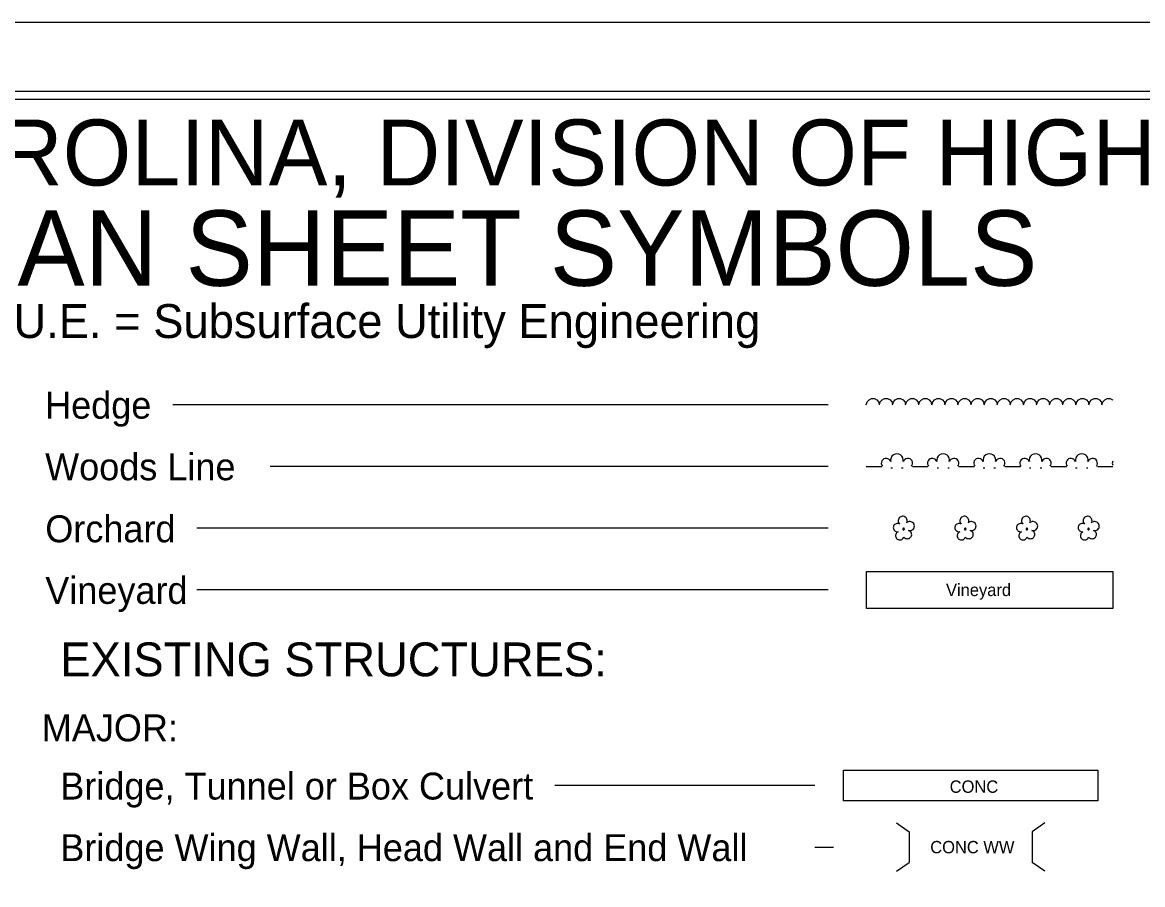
# Model space of a CAD drawing. Extents: x 1729964 to 1731648, y 539487 to 540587.
# Drawn here: x 1730887.2 to 1731250.8, y 540307.4 to 540587.4 of the extents above; entities that cross this region are included whole.
import ezdxf

# ---------------------------------------------------------------- set-up
doc = ezdxf.new("R2010")
doc.units = 0
for name, color, linetype in [('Sheet Cutting Line CELL', 7, 'Continuous'), ('Sheet Plot Border Inside CELL', 7, 'Continuous'), ('Sheet Plot Border Outside CELL', 7, 'Continuous'), ('Sheet Symbology CELL', 7, 'Continuous')]:
    doc.layers.add(name, color=color, linetype=linetype)

msp = doc.modelspace()

# ---------------------------------------------------------------- linework, layer by layer
at = {"layer": 'Sheet Cutting Line CELL'}
msp.add_line((1731648.46, 540587.38), (1729964.46, 540587.38), dxfattribs=at)
at = {"layer": 'Sheet Plot Border Inside CELL'}
msp.add_lwpolyline([(1729977.46, 539509.83), (1731643.96, 539509.83), (1731643.96, 540564.93), (1729977.46, 540564.93)], close=True, dxfattribs=at)
at = {"layer": 'Sheet Plot Border Outside CELL'}
msp.add_lwpolyline([(1729964.46, 539487.38), (1731648.46, 539487.38), (1731648.46, 540587.38), (1729964.46, 540587.38)], close=True, dxfattribs=at)
at = {"layer": 'Sheet Symbology CELL'}
for p, q in [((1731148.74, 540463.23), (1730936.06, 540463.23)), ((1731161.14, 540463.23), (1731161.44, 540464.18)), ((1731161.44, 540464.18), (1731162.04, 540464.83)), ((1731162.04, 540464.83), (1731162.84, 540465.28)), ((1731162.84, 540465.28), (1731163.79, 540465.28)), ((1731163.79, 540465.28), (1731164.59, 540464.78)), ((1731164.59, 540464.78), (1731165.14, 540464.13)), ((1731165.14, 540464.13), (1731165.34, 540463.28)), ((1731165.39, 540463.23), (1731165.69, 540464.18)), ((1731165.69, 540464.18), (1731166.29, 540464.83)), ((1731166.29, 540464.83), (1731167.09, 540465.28)), ((1731167.09, 540465.28), (1731168.04, 540465.28)), ((1731168.04, 540465.28), (1731168.84, 540464.78)), ((1731168.84, 540464.78), (1731169.39, 540464.13)), ((1731169.39, 540464.13), (1731169.59, 540463.28)), ((1731169.64, 540463.23), (1731169.94, 540464.18)), ((1731169.94, 540464.18), (1731170.54, 540464.83)), ((1731170.54, 540464.83), (1731171.34, 540465.28)), ((1731171.34, 540465.28), (1731172.29, 540465.28)), ((1731172.29, 540465.28), (1731173.09, 540464.78)), ((1731173.09, 540464.78), (1731173.64, 540464.13)), ((1731173.64, 540464.13), (1731173.84, 540463.28)), ((1731173.89, 540463.23), (1731174.19, 540464.18)), ((1731174.19, 540464.18), (1731174.79, 540464.83)), ((1731174.79, 540464.83), (1731175.59, 540465.28)), ((1731175.59, 540465.28), (1731176.54, 540465.28)), ((1731176.54, 540465.28), (1731177.34, 540464.78)), ((1731177.34, 540464.78), (1731177.89, 540464.13)), ((1731177.89, 540464.13), (1731178.09, 540463.28)), ((1731178.14, 540463.23), (1731178.44, 540464.18)), ((1731178.44, 540464.18), (1731179.04, 540464.83)), ((1731179.04, 540464.83), (1731179.84, 540465.28)), ((1731179.84, 540465.28), (1731180.79, 540465.28)), ((1731180.79, 540465.28), (1731181.59, 540464.78)), ((1731181.59, 540464.78), (1731182.14, 540464.13)), ((1731182.14, 540464.13), (1731182.34, 540463.28)), ((1731182.39, 540463.23), (1731182.69, 540464.18)), ((1731182.69, 540464.18), (1731183.29, 540464.83)), ((1731183.29, 540464.83), (1731184.09, 540465.28)), ((1731184.09, 540465.28), (1731185.04, 540465.28)), ((1731185.04, 540465.28), (1731185.84, 540464.78)), ((1731185.84, 540464.78), (1731186.39, 540464.13)), ((1731186.39, 540464.13), (1731186.59, 540463.28)), ((1731186.64, 540463.23), (1731186.94, 540464.18)), ((1731186.94, 540464.18), (1731187.54, 540464.83)), ((1731187.54, 540464.83), (1731188.34, 540465.28)), ((1731188.34, 540465.28), (1731189.29, 540465.28)), ((1731189.29, 540465.28), (1731190.09, 540464.78)), ((1731190.09, 540464.78), (1731190.64, 540464.13)), ((1731190.64, 540464.13), (1731190.84, 540463.28)), ((1731190.89, 540463.23), (1731191.19, 540464.18)), ((1731191.19, 540464.18), (1731191.79, 540464.83)), ((1731191.79, 540464.83), (1731192.59, 540465.28)), ((1731192.59, 540465.28), (1731193.54, 540465.28)), ((1731193.54, 540465.28), (1731194.34, 540464.78)), ((1731194.34, 540464.78), (1731194.89, 540464.13)), ((1731194.89, 540464.13), (1731195.09, 540463.28)), ((1731195.14, 540463.23), (1731195.44, 540464.18)), ((1731195.44, 540464.18), (1731196.04, 540464.83)), ((1731196.04, 540464.83), (1731196.84, 540465.28)), ((1731196.84, 540465.28), (1731197.79, 540465.28)), ((1731197.79, 540465.28), (1731198.59, 540464.78)), ((1731198.59, 540464.78), (1731199.14, 540464.13)), ((1731199.14, 540464.13), (1731199.34, 540463.28)), ((1731199.39, 540463.23), (1731199.69, 540464.18)), ((1731199.69, 540464.18), (1731200.29, 540464.83)), ((1731200.29, 540464.83), (1731201.09, 540465.28)), ((1731201.09, 540465.28), (1731202.04, 540465.28)), ((1731202.04, 540465.28), (1731202.84, 540464.78)), ((1731202.84, 540464.78), (1731203.39, 540464.13)), ((1731203.39, 540464.13), (1731203.59, 540463.28)), ((1731203.64, 540463.23), (1731203.94, 540464.18)), ((1731203.94, 540464.18), (1731204.54, 540464.83)), ((1731204.54, 540464.83), (1731205.34, 540465.28)), ((1731205.34, 540465.28), (1731206.29, 540465.28)), ((1731206.29, 540465.28), (1731207.09, 540464.78)), ((1731207.09, 540464.78), (1731207.64, 540464.13)), ((1731207.64, 540464.13), (1731207.84, 540463.28)), ((1731207.89, 540463.23), (1731208.19, 540464.18)), ((1731208.19, 540464.18), (1731208.79, 540464.83)), ((1731208.79, 540464.83), (1731209.59, 540465.28)), ((1731209.59, 540465.28), (1731210.54, 540465.28)), ((1731210.54, 540465.28), (1731211.34, 540464.78)), ((1731211.34, 540464.78), (1731211.89, 540464.13)), ((1731211.89, 540464.13), (1731212.09, 540463.28)), ((1731212.14, 540463.23), (1731212.44, 540464.18)), ((1731212.44, 540464.18), (1731213.04, 540464.83)), ((1731213.04, 540464.83), (1731213.84, 540465.28)), ((1731213.84, 540465.28), (1731214.79, 540465.28)), ((1731214.79, 540465.28), (1731215.59, 540464.78)), ((1731215.59, 540464.78), (1731216.14, 540464.13)), ((1731216.14, 540464.13), (1731216.34, 540463.28)), ((1731216.39, 540463.23), (1731216.69, 540464.18)), ((1731216.69, 540464.18), (1731217.29, 540464.83)), ((1731217.29, 540464.83), (1731218.09, 540465.28)), ((1731218.09, 540465.28), (1731219.04, 540465.28)), ((1731219.04, 540465.28), (1731219.84, 540464.78)), ((1731219.84, 540464.78), (1731220.39, 540464.13)), ((1731220.39, 540464.13), (1731220.59, 540463.28)), ((1731220.64, 540463.23), (1731220.94, 540464.18)), ((1731220.94, 540464.18), (1731221.54, 540464.83)), ((1731221.54, 540464.83), (1731222.34, 540465.28)), ((1731222.34, 540465.28), (1731223.29, 540465.28)), ((1731223.29, 540465.28), (1731224.09, 540464.78)), ((1731224.09, 540464.78), (1731224.64, 540464.13)), ((1731224.64, 540464.13), (1731224.84, 540463.28)), ((1731224.89, 540463.23), (1731225.19, 540464.18)), ((1731225.19, 540464.18), (1731225.79, 540464.83)), ((1731225.79, 540464.83), (1731226.59, 540465.28)), ((1731226.59, 540465.28), (1731227.54, 540465.28)), ((1731227.54, 540465.28), (1731228.34, 540464.78)), ((1731228.34, 540464.78), (1731228.89, 540464.13)), ((1731228.89, 540464.13), (1731229.09, 540463.28)), ((1731229.14, 540463.23), (1731229.44, 540464.18)), ((1731229.44, 540464.18), (1731230.04, 540464.83)), ((1731230.04, 540464.83), (1731230.84, 540465.28)), ((1731230.84, 540465.28), (1731231.79, 540465.28)), ((1731231.79, 540465.28), (1731232.59, 540464.78)), ((1731232.59, 540464.78), (1731233.14, 540464.13)), ((1731233.14, 540464.13), (1731233.34, 540463.28)), ((1731233.39, 540463.23), (1731233.69, 540464.18)), ((1731233.69, 540464.18), (1731234.29, 540464.83)), ((1731234.29, 540464.83), (1731235.09, 540465.28)), ((1731235.09, 540465.28), (1731236.04, 540465.28)), ((1731236.04, 540465.28), (1731236.84, 540464.78)), ((1731236.84, 540464.78), (1731237.39, 540464.13)), ((1731237.39, 540464.13), (1731237.59, 540463.28)), ((1731237.64, 540463.23), (1731237.94, 540464.18)), ((1731237.94, 540464.18), (1731238.54, 540464.83)), ((1731238.54, 540464.83), (1731239.34, 540465.28)), ((1731239.34, 540465.28), (1731240.29, 540465.28)), ((1731240.29, 540465.28), (1731241.09, 540464.78)), ((1731241.09, 540464.78), (1731241.14, 540464.73)), ((1731148.74, 540443.23), (1730967.62, 540443.23)), ((1731161.14, 540443.23), (1731166.14, 540443.23)), ((1731169.09, 540442.73), (1731169.59, 540442.73)), ((1731172.59, 540442.73), (1731173.09, 540442.73)), ((1731176.14, 540443.23), (1731181.14, 540443.23)), ((1731184.09, 540442.73), (1731184.59, 540442.73)), ((1731187.59, 540442.73), (1731188.09, 540442.73)), ((1731191.14, 540443.23), (1731196.14, 540443.23)), ((1731199.09, 540442.73), (1731199.59, 540442.73)), ((1731202.59, 540442.73), (1731203.09, 540442.73)), ((1731206.14, 540443.23), (1731211.14, 540443.23)), ((1731214.09, 540442.73), (1731214.59, 540442.73)), ((1731217.59, 540442.73), (1731218.09, 540442.73)), ((1731221.14, 540443.23), (1731226.14, 540443.23)), ((1731229.09, 540442.73), (1731229.59, 540442.73)), ((1731232.59, 540442.73), (1731233.09, 540442.73)), ((1731236.14, 540443.23), (1731241.14, 540443.23)), ((1731148.79, 540423.1), (1730943.85, 540423.1)), ((1731148.79, 540403.1), (1730943.85, 540403.1)), ((1731144.48, 540339.59), (1731060.05, 540339.59)), ((1731170.93, 540327.45), (1731175.03, 540324.59)), ((1731219.13, 540327.45), (1731215.03, 540324.59)), ((1731175.03, 540324.59), (1731175.03, 540314.59)), ((1731215.03, 540324.59), (1731215.03, 540314.59)), ((1731144.48, 540319.59), (1731150.46, 540319.59)), ((1731170.93, 540311.73), (1731175.03, 540314.59)), ((1731219.13, 540311.73), (1731215.03, 540314.59))]:
    msp.add_line(p, q, dxfattribs=at)
msp.add_lwpolyline([(1731631.46, 540562.38), (1730131.46, 540562.38), (1730131.46, 539513.4), (1731631.46, 539513.4)], close=True, dxfattribs=at)
for points in [[(1731174.23, 540424.85), (1731174.38, 540425.15), (1731174.43, 540425.45), (1731174.38, 540425.75), (1731174.33, 540426.05), (1731174.18, 540426.3), (1731174.03, 540426.55), (1731173.78, 540426.75), (1731173.53, 540426.9), (1731173.18, 540427), (1731172.93, 540427), (1731172.63, 540426.95), (1731172.33, 540426.85), (1731172.08, 540426.7), (1731171.83, 540426.5), (1731171.68, 540426.2), (1731171.58, 540425.95), (1731171.53, 540425.65), (1731171.53, 540425.35), (1731171.58, 540425.05), (1731171.73, 540424.8), (1731171.93, 540424.5), (1731171.68, 540424.65), (1731171.38, 540424.7), (1731171.08, 540424.7), (1731170.83, 540424.6), (1731170.58, 540424.5), (1731170.33, 540424.3), (1731170.13, 540424.1), (1731169.98, 540423.85), (1731169.93, 540423.6), (1731169.88, 540423.25), (1731169.93, 540423), (1731170.03, 540422.75), (1731170.23, 540422.5), (1731170.38, 540422.3), (1731170.63, 540422.15), (1731170.93, 540422), (1731171.18, 540421.95), (1731171.48, 540421.95), (1731171.23, 540421.85), (1731170.98, 540421.65), (1731170.83, 540421.45), (1731170.73, 540421.15), (1731170.63, 540420.85), (1731170.63, 540420.6), (1731170.68, 540420.3), (1731170.83, 540420.05), (1731170.98, 540419.8), (1731171.18, 540419.6), (1731171.43, 540419.45), (1731171.68, 540419.35), (1731171.98, 540419.35), (1731172.28, 540419.35), (1731172.53, 540419.4), (1731172.78, 540419.6), (1731173.03, 540419.75), (1731173.28, 540420.2)], [(1731194.23, 540424.85), (1731194.38, 540425.15), (1731194.43, 540425.45), (1731194.38, 540425.75), (1731194.33, 540426.05), (1731194.18, 540426.3), (1731194.03, 540426.55), (1731193.78, 540426.75), (1731193.53, 540426.9), (1731193.18, 540427), (1731192.93, 540427), (1731192.63, 540426.95), (1731192.33, 540426.85), (1731192.08, 540426.7), (1731191.83, 540426.5), (1731191.68, 540426.2), (1731191.58, 540425.95), (1731191.53, 540425.65), (1731191.53, 540425.35), (1731191.58, 540425.05), (1731191.73, 540424.8), (1731191.93, 540424.5), (1731191.68, 540424.65), (1731191.38, 540424.7), (1731191.08, 540424.7), (1731190.83, 540424.6), (1731190.58, 540424.5), (1731190.33, 540424.3), (1731190.13, 540424.1), (1731189.98, 540423.85), (1731189.93, 540423.6), (1731189.88, 540423.25), (1731189.93, 540423), (1731190.03, 540422.75), (1731190.23, 540422.5), (1731190.38, 540422.3), (1731190.63, 540422.15), (1731190.93, 540422), (1731191.18, 540421.95), (1731191.48, 540421.95), (1731191.23, 540421.85), (1731190.98, 540421.65), (1731190.83, 540421.45), (1731190.73, 540421.15), (1731190.63, 540420.85), (1731190.63, 540420.6), (1731190.68, 540420.3), (1731190.83, 540420.05), (1731190.98, 540419.8), (1731191.18, 540419.6), (1731191.43, 540419.45), (1731191.68, 540419.35), (1731191.98, 540419.35), (1731192.28, 540419.35), (1731192.53, 540419.4), (1731192.78, 540419.6), (1731193.03, 540419.75), (1731193.28, 540420.2)], [(1731214.23, 540424.85), (1731214.38, 540425.15), (1731214.43, 540425.45), (1731214.38, 540425.75), (1731214.33, 540426.05), (1731214.18, 540426.3), (1731214.03, 540426.55), (1731213.78, 540426.75), (1731213.53, 540426.9), (1731213.18, 540427), (1731212.93, 540427), (1731212.63, 540426.95), (1731212.33, 540426.85), (1731212.08, 540426.7), (1731211.83, 540426.5), (1731211.68, 540426.2), (1731211.58, 540425.95), (1731211.53, 540425.65), (1731211.53, 540425.35), (1731211.58, 540425.05), (1731211.73, 540424.8), (1731211.93, 540424.5), (1731211.68, 540424.65), (1731211.38, 540424.7), (1731211.08, 540424.7), (1731210.83, 540424.6), (1731210.58, 540424.5), (1731210.33, 540424.3), (1731210.13, 540424.1), (1731209.98, 540423.85), (1731209.93, 540423.6), (1731209.88, 540423.25), (1731209.93, 540423), (1731210.03, 540422.75), (1731210.23, 540422.5), (1731210.38, 540422.3), (1731210.63, 540422.15), (1731210.93, 540422), (1731211.18, 540421.95), (1731211.48, 540421.95), (1731211.23, 540421.85), (1731210.98, 540421.65), (1731210.83, 540421.45), (1731210.73, 540421.15), (1731210.63, 540420.85), (1731210.63, 540420.6), (1731210.68, 540420.3), (1731210.83, 540420.05), (1731210.98, 540419.8), (1731211.18, 540419.6), (1731211.43, 540419.45), (1731211.68, 540419.35), (1731211.98, 540419.35), (1731212.28, 540419.35), (1731212.53, 540419.4), (1731212.78, 540419.6), (1731213.03, 540419.75), (1731213.28, 540420.2)], [(1731234.23, 540424.85), (1731234.38, 540425.15), (1731234.43, 540425.45), (1731234.38, 540425.75), (1731234.33, 540426.05), (1731234.18, 540426.3), (1731234.03, 540426.55), (1731233.78, 540426.75), (1731233.53, 540426.9), (1731233.18, 540427), (1731232.93, 540427), (1731232.63, 540426.95), (1731232.33, 540426.85), (1731232.08, 540426.7), (1731231.83, 540426.5), (1731231.68, 540426.2), (1731231.58, 540425.95), (1731231.53, 540425.65), (1731231.53, 540425.35), (1731231.58, 540425.05), (1731231.73, 540424.8), (1731231.93, 540424.5), (1731231.68, 540424.65), (1731231.38, 540424.7), (1731231.08, 540424.7), (1731230.83, 540424.6), (1731230.58, 540424.5), (1731230.33, 540424.3), (1731230.13, 540424.1), (1731229.98, 540423.85), (1731229.93, 540423.6), (1731229.88, 540423.25), (1731229.93, 540423), (1731230.03, 540422.75), (1731230.23, 540422.5), (1731230.38, 540422.3), (1731230.63, 540422.15), (1731230.93, 540422), (1731231.18, 540421.95), (1731231.48, 540421.95), (1731231.23, 540421.85), (1731230.98, 540421.65), (1731230.83, 540421.45), (1731230.73, 540421.15), (1731230.63, 540420.85), (1731230.63, 540420.6), (1731230.68, 540420.3), (1731230.83, 540420.05), (1731230.98, 540419.8), (1731231.18, 540419.6), (1731231.43, 540419.45), (1731231.68, 540419.35), (1731231.98, 540419.35), (1731232.28, 540419.35), (1731232.53, 540419.4), (1731232.78, 540419.6), (1731233.03, 540419.75), (1731233.28, 540420.2)], [(1731173.28, 540420.2), (1731173.88, 540419.85), (1731174.18, 540419.75), (1731174.48, 540419.7), (1731174.78, 540419.75), (1731175.03, 540419.85), (1731175.28, 540420), (1731175.53, 540420.2), (1731175.68, 540420.45), (1731175.78, 540420.7), (1731175.88, 540421), (1731175.83, 540421.3), (1731175.78, 540421.6), (1731175.58, 540421.9), (1731175.43, 540422.1), (1731175.18, 540422.25), (1731174.88, 540422.4), (1731175.18, 540422.35), (1731175.53, 540422.35), (1731175.78, 540422.45), (1731176.08, 540422.6), (1731176.33, 540422.75), (1731176.53, 540423), (1731176.68, 540423.3), (1731176.73, 540423.6), (1731176.78, 540423.9), (1731176.73, 540424.2), (1731176.63, 540424.5), (1731176.43, 540424.75), (1731176.18, 540425), (1731175.93, 540425.15), (1731175.63, 540425.25), (1731175.33, 540425.3), (1731175.03, 540425.3), (1731174.73, 540425.2), (1731174.48, 540425.05), (1731174.23, 540424.85)], [(1731193.28, 540420.2), (1731193.88, 540419.85), (1731194.18, 540419.75), (1731194.48, 540419.7), (1731194.78, 540419.75), (1731195.03, 540419.85), (1731195.28, 540420), (1731195.53, 540420.2), (1731195.68, 540420.45), (1731195.78, 540420.7), (1731195.88, 540421), (1731195.83, 540421.3), (1731195.78, 540421.6), (1731195.58, 540421.9), (1731195.43, 540422.1), (1731195.18, 540422.25), (1731194.88, 540422.4), (1731195.18, 540422.35), (1731195.53, 540422.35), (1731195.78, 540422.45), (1731196.08, 540422.6), (1731196.33, 540422.75), (1731196.53, 540423), (1731196.68, 540423.3), (1731196.73, 540423.6), (1731196.78, 540423.9), (1731196.73, 540424.2), (1731196.63, 540424.5), (1731196.43, 540424.75), (1731196.18, 540425), (1731195.93, 540425.15), (1731195.63, 540425.25), (1731195.33, 540425.3), (1731195.03, 540425.3), (1731194.73, 540425.2), (1731194.48, 540425.05), (1731194.23, 540424.85)], [(1731213.28, 540420.2), (1731213.88, 540419.85), (1731214.18, 540419.75), (1731214.48, 540419.7), (1731214.78, 540419.75), (1731215.03, 540419.85), (1731215.28, 540420), (1731215.53, 540420.2), (1731215.68, 540420.45), (1731215.78, 540420.7), (1731215.88, 540421), (1731215.83, 540421.3), (1731215.78, 540421.6), (1731215.58, 540421.9), (1731215.43, 540422.1), (1731215.18, 540422.25), (1731214.88, 540422.4), (1731215.18, 540422.35), (1731215.53, 540422.35), (1731215.78, 540422.45), (1731216.08, 540422.6), (1731216.33, 540422.75), (1731216.53, 540423), (1731216.68, 540423.3), (1731216.73, 540423.6), (1731216.78, 540423.9), (1731216.73, 540424.2), (1731216.63, 540424.5), (1731216.43, 540424.75), (1731216.18, 540425), (1731215.93, 540425.15), (1731215.63, 540425.25), (1731215.33, 540425.3), (1731215.03, 540425.3), (1731214.73, 540425.2), (1731214.48, 540425.05), (1731214.23, 540424.85)], [(1731233.28, 540420.2), (1731233.88, 540419.85), (1731234.18, 540419.75), (1731234.48, 540419.7), (1731234.78, 540419.75), (1731235.03, 540419.85), (1731235.28, 540420), (1731235.53, 540420.2), (1731235.68, 540420.45), (1731235.78, 540420.7), (1731235.88, 540421), (1731235.83, 540421.3), (1731235.78, 540421.6), (1731235.58, 540421.9), (1731235.43, 540422.1), (1731235.18, 540422.25), (1731234.88, 540422.4), (1731235.18, 540422.35), (1731235.53, 540422.35), (1731235.78, 540422.45), (1731236.08, 540422.6), (1731236.33, 540422.75), (1731236.53, 540423), (1731236.68, 540423.3), (1731236.73, 540423.6), (1731236.78, 540423.9), (1731236.73, 540424.2), (1731236.63, 540424.5), (1731236.43, 540424.75), (1731236.18, 540425), (1731235.93, 540425.15), (1731235.63, 540425.25), (1731235.33, 540425.3), (1731235.03, 540425.3), (1731234.73, 540425.2), (1731234.48, 540425.05), (1731234.23, 540424.85)], [(1731173.38, 540423.1), (1731173.23, 540423.1), (1731173.13, 540423.05), (1731173.03, 540423), (1731173.03, 540422.85), (1731173.03, 540422.75), (1731173.13, 540422.65), (1731173.28, 540422.65), (1731173.38, 540422.65), (1731173.48, 540422.75), (1731173.53, 540422.9), (1731173.48, 540423), (1731173.38, 540423.1)], [(1731193.38, 540423.1), (1731193.23, 540423.1), (1731193.13, 540423.05), (1731193.03, 540423), (1731193.03, 540422.85), (1731193.03, 540422.75), (1731193.13, 540422.65), (1731193.28, 540422.65), (1731193.38, 540422.65), (1731193.48, 540422.75), (1731193.53, 540422.9), (1731193.48, 540423), (1731193.38, 540423.1)], [(1731213.38, 540423.1), (1731213.23, 540423.1), (1731213.13, 540423.05), (1731213.03, 540423), (1731213.03, 540422.85), (1731213.03, 540422.75), (1731213.13, 540422.65), (1731213.28, 540422.65), (1731213.38, 540422.65), (1731213.48, 540422.75), (1731213.53, 540422.9), (1731213.48, 540423), (1731213.38, 540423.1)], [(1731233.38, 540423.1), (1731233.23, 540423.1), (1731233.13, 540423.05), (1731233.03, 540423), (1731233.03, 540422.85), (1731233.03, 540422.75), (1731233.13, 540422.65), (1731233.28, 540422.65), (1731233.38, 540422.65), (1731233.48, 540422.75), (1731233.53, 540422.9), (1731233.48, 540423), (1731233.38, 540423.1)], [(1731161.18, 540409.1), (1731241.18, 540409.1), (1731241.18, 540397.1), (1731161.18, 540397.1), (1731161.18, 540409.1)], [(1731153.78, 540344.59), (1731236.28, 540344.59), (1731236.28, 540334.59), (1731153.78, 540334.59), (1731153.78, 540344.59)]]:
    msp.add_lwpolyline(points, dxfattribs=at)
for centre, radius, start, end in [((1731167.59, 540444.25), 1.58, 18.435, 219.2315), ((1731171.09, 540445.25), 2.06, 345.9638, 194.0362), ((1731174.59, 540444.25), 1.58, 320.7685, 161.5651), ((1731182.58, 540444.25), 1.58, 18.435, 219.2315), ((1731186.08, 540445.25), 2.06, 345.9638, 194.0362), ((1731189.58, 540444.25), 1.58, 320.7685, 161.5651), ((1731197.58, 540444.25), 1.58, 18.435, 219.2315), ((1731201.08, 540445.25), 2.06, 345.9638, 194.0362), ((1731204.58, 540444.25), 1.58, 320.7685, 161.5651), ((1731212.58, 540444.25), 1.58, 18.435, 219.2315), ((1731216.08, 540445.25), 2.06, 345.9638, 194.0362), ((1731219.58, 540444.25), 1.58, 320.7685, 161.5651), ((1731227.58, 540444.25), 1.58, 18.435, 219.2315), ((1731231.08, 540445.25), 2.06, 345.9638, 194.0362), ((1731234.58, 540444.25), 1.58, 320.7685, 161.5651), ((1731242.58, 540444.25), 1.58, 156.251, 203.749)]:
    msp.add_arc(centre, radius, start, end, dxfattribs=at)

# ---------------------------------------------------------------- texts
for s, height, p in [('STATE OF NORTH CAROLINA, DIVISION OF HIGHWAYS', 21.419, (1730582.03, 540534.42)), ('CONVENTIONAL  PLAN SHEET SYMBOLS', 24.4803, (1730569.07, 540501.85)), ('Hedge', 8.75, (1730894.58, 540458.71)), ('Woods Line', 8.75, (1730894.58, 540438.71)), ('Orchard', 8.75, (1730894.63, 540418.57)), ('Vineyard', 8.75, (1730894.63, 540398.57)), ('EXISTING STRUCTURES:', 11, (1730899.51, 540375.04)), ('MAJOR:', 8.75, (1730893.49, 540353.93)), ('Bridge, Tunnel or Box Culvert', 8.75, (1730899.51, 540335.04)), ('CONC', 4, (1731188.21, 540337.23)), ('Bridge Wing Wall, Head Wall and End Wall', 8.75, (1730899.51, 540315.04))]:
    msp.add_text(s, height=height, dxfattribs=at).set_placement(p)
for s, height, rotation, p in [('*S.U.E. = Subsurface Utility Engineering', 11, 360, (1730864.68, 540484.89)), ('Vineyard', 4, 0, (1731187.01, 540401.1)), ('CONC WW', 4, 0, (1731181.9, 540317.59))]:
    msp.add_text(s, height=height, rotation=rotation, dxfattribs=at).set_placement(p)

doc.saveas('drawing.dxf')
